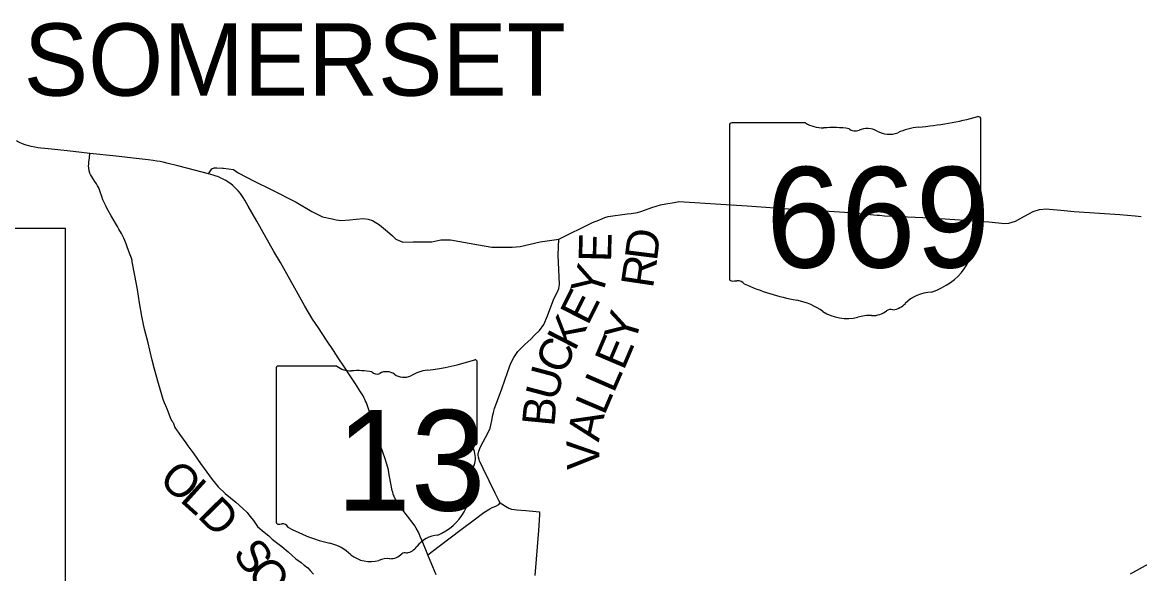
# Model space of a CAD drawing. Extents: x 1761803 to 2441803, y 509895 to 949895.
# Drawn here: x 2027446 to 2058370, y 738164 to 753419 of the extents above; entities that cross this region are included whole.
import ezdxf

# ---------------------------------------------------------------- set-up
doc = ezdxf.new("R2010")
doc.units = 0
for name, color, linetype in [('GM_X_County_Road', 7, 'Continuous'), ('GM_X_Minor_Lake', 7, 'Continuous'), ('GM_X_State_Location', 7, 'Continuous'), ('GM_X_Township_Road', 7, 'Continuous')]:
    doc.layers.add(name, color=color, linetype=linetype)

msp = doc.modelspace()

# ---------------------------------------------------------------- linework, layer by layer
at = {"layer": 'GM_X_County_Road'}
for points in [[(2039594, 739384), (2039954, 739654), (2040218, 739852), (2040380, 739960), (2040452, 739997), (2040553, 740031), (2040634, 740082), (2040672, 740126), (2040638, 740187), (2040533, 740390), (2040198, 741071), (2040099, 741288), (2040086, 741325), (2040068, 741389), (2040059, 741447), (2040061, 741475), (2040079, 741550), (2040126, 741670), (2040339, 742070), (2040393, 742194), (2040416, 742271), (2040441, 742402), (2040466, 742556), (2040484, 742627), (2040515, 742733), (2040721, 743277), (2040885, 743760), (2040969, 743987), (2041048, 744145), (2041156, 744311), (2041355, 744508), (2041516, 744655), (2041630, 744769), (2041761, 744895), (2041878, 745055), (2041977, 745301), (2042159, 745768), (2042268, 745980), (2042294, 746058), (2042314, 746164), (2042278, 746987), (2042296, 747418)], [(2031622, 742343), (2031670, 742205), (2031823, 741985), (2031970, 741780), (2032027, 741700), (2032194, 741483), (2032378, 741213), (2032551, 740968), (2032696, 740771), (2032862, 740563), (2033063, 740386), (2033350, 740138), (2033545, 739967), (2033672, 739853), (2033743, 739751), (2033843, 739634), (2033952, 739472), (2034097, 739347), (2034264, 739210), (2034361, 739118), (2034441, 739057), (2034519, 739001), (2034630, 738918), (2034799, 738772), (2034913, 738671), (2035016, 738579), (2035159, 738472), (2035245, 738397), (2035346, 738325), (2035414, 738255), (2035501, 738148)], [(2040672, 740126), (2040817, 740031), (2040912, 739977), (2040980, 739953), (2041131, 739928), (2041378, 739911), (2041665, 739882), (2041761, 739871)], [(2041761, 739871), (2041761, 739795), (2041730, 739361), (2041632, 738116)], [(2038673, 738681), (2038981, 738924), (2039594, 739384)]]:
    msp.add_lwpolyline(points, dxfattribs=at)
at = {"layer": 'GM_X_Minor_Lake'}
for points in [[(2029314, 749794), (2028855, 749843), (2028347, 749898), (2028069, 749928), (2027955, 749942), (2027875, 749951), (2027790, 749964), (2027693, 749981), (2027625, 749998), (2027555, 750018), (2027499, 750038), (2027431, 750065), (2027381, 750088), (2027315, 750121), (2027288, 750137)], [(2029510, 748931), (2029495, 748954), (2029452, 749018), (2029406, 749089), (2029359, 749164), (2029333, 749212), (2029318, 749247), (2029297, 749311), (2029282, 749390), (2029280, 749440), (2029282, 749497), (2029288, 749551), (2029300, 749667), (2029314, 749794)], [(2032601, 749227), (2031997, 749386), (2031753, 749451), (2031448, 749526), (2031345, 749548), (2031259, 749565), (2031167, 749582), (2031064, 749598), (2030931, 749617), (2030599, 749656), (2030042, 749715), (2029314, 749794)], [(2032601, 749227), (2032693, 749368), (2032752, 749390), (2032833, 749395), (2032985, 749385), (2033017, 749381)], [(2033017, 749381), (2033291, 749347), (2033423, 749259), (2033881, 749020), (2034330, 748790), (2035022, 748441), (2035462, 748190), (2035755, 748040), (2036017, 747985), (2036133, 747951), (2036256, 747933), (2036510, 747953), (2036686, 747975), (2036883, 747989), (2037015, 747971), (2037137, 747933), (2037327, 747820), (2037554, 747636), (2037690, 747514), (2037784, 747421), (2037974, 747341), (2038267, 747344), (2038783, 747350), (2039031, 747401), (2039169, 747404), (2039300, 747401), (2040070, 747263), (2040439, 747196), (2041002, 747196), (2041220, 747213), (2041780, 747347), (2042296, 747418), (2043224, 747880), (2043398, 747949), (2043568, 748019), (2043664, 748047), (2044184, 748119), (2044298, 748133), (2044467, 748155), (2044595, 748191), (2044865, 748293), (2045107, 748367), (2045255, 748395), (2045489, 748439), (2045577, 748455), (2045617, 748461), (2046058, 748437), (2046633, 748398), (2047506, 748339), (2048785, 748250), (2049640, 748208), (2050339, 748160), (2051101, 748087), (2051172, 748081), (2051310, 748069), (2052577, 748007), (2054191, 747896), (2054639, 747858), (2054751, 747864), (2054931, 747914), (2055186, 748058), (2055424, 748190), (2055598, 748238), (2055792, 748258), (2055871, 748252), (2056188, 748226), (2056559, 748190), (2057822, 748101), (2058247, 748065), (2058411, 748043)], [(2033700, 748332), (2033654, 748414), (2033600, 748501), (2033555, 748574), (2033518, 748631), (2033479, 748683), (2033422, 748753), (2033372, 748808), (2033330, 748848), (2033267, 748905), (2033215, 748947), (2033138, 749000), (2033075, 749041), (2033004, 749080), (2032957, 749103), (2032891, 749132), (2032850, 749150), (2032806, 749165), (2032728, 749190), (2032601, 749227)], [(2031622, 742343), (2031604, 742369), (2031588, 742393), (2031566, 742430), (2031546, 742475), (2031507, 742576), (2031460, 742694), (2031414, 742804), (2031381, 742888), (2031345, 742987), (2031309, 743109), (2031217, 743425), (2031107, 743820), (2031041, 744071), (2030974, 744350), (2030925, 744555), (2030826, 744929), (2030788, 745105), (2030755, 745287), (2030692, 745662), (2030631, 746028), (2030560, 746412), (2030489, 746795), (2030483, 746826), (2030465, 746890), (2030432, 746985), (2030359, 747184), (2030320, 747287), (2030281, 747385), (2030253, 747449), (2030190, 747574), (2030119, 747698), (2030078, 747771), (2029902, 748068), (2029820, 748212), (2029781, 748281), (2029752, 748339), (2029715, 748420), (2029677, 748511), (2029648, 748598), (2029602, 748733), (2029583, 748786), (2029560, 748839), (2029530, 748897), (2029510, 748931)], [(2038902, 738130), (2038807, 738356), (2038737, 738526), (2038673, 738681), (2038531, 739022), (2038503, 739090), (2038460, 739190), (2038428, 739266), (2038407, 739310), (2038346, 739424), (2038307, 739487), (2038262, 739551), (2038104, 739758), (2037953, 739955), (2037876, 740058), (2037843, 740106), (2037791, 740189), (2037767, 740235), (2037738, 740302), (2037713, 740364), (2037697, 740420), (2037684, 740469), (2037639, 740703), (2037593, 740958), (2037577, 741034), (2037558, 741100), (2037483, 741343), (2037362, 741709), (2037252, 742035), (2037158, 742321), (2037060, 742615), (2036967, 742888), (2036946, 742941), (2036929, 742981), (2036910, 743021), (2036878, 743082), (2036805, 743200), (2036663, 743415), (2036573, 743551), (2036534, 743612), (2036358, 743881), (2036188, 744139), (2036055, 744338), (2035863, 744629), (2035639, 744963), (2035477, 745209), (2035267, 745563), (2035035, 745977), (2034587, 746772), (2034410, 747081), (2033932, 747921), (2033700, 748332)], [(2058113, 738160), (2058182, 738196), (2058634, 738445)]]:
    msp.add_lwpolyline(points, dxfattribs=at)
at = {"layer": 'GM_X_State_Location'}
msp.add_lwpolyline([(1999264, 732882), (2028640, 732882), (2028640, 747716), (1999264, 747716)], close=True, dxfattribs=at)
at = {"layer": 'GM_X_Township_Road'}
for p, q in [((2047014, 750563), (2047014, 746336)), ((2049121, 750635), (2047082, 750635)), ((2053974, 748529), (2053974, 750740)), ((2053974, 748530), (2053974, 748529)), ((2034467, 743837), (2034467, 739610)), ((2036153, 743909), (2034522, 743909)), ((2040036, 741803), (2040036, 744014)), ((2040036, 741804), (2040036, 741803))]:
    msp.add_line(p, q, dxfattribs=at)
for centre, radius, start, end in [((2038052, 749671), 5905, 275.8445, 288.9065), ((2039974, 744023), 62, 351.8621, 97.738), ((2034531, 743846), 64.5, 98.1301, 188.1301), ((2036541, 744400), 626, 231.6195, 271.1119), ((2036749, 741536), 2246, 80.4867, 94.9883), ((2037259, 743867), 181, 219.7921, 297.1024), ((2037524, 743379), 375, 54.4667, 119.1411), ((2038806, 742618), 1188, 97.3462, 120.7689), ((2038008, 744049), 452, 233.8562, 294.8282), ((2040022, 741641), 95.9, 107.944, 210.337), ((2039411, 741361), 576, 340.033, 23.6496), ((2039970, 741795), 66.3, 289.6038, 7.7341), ((2040258, 740878), 419, 136.8065, 186.9296), ((2038383, 740597), 1477, 292.3089, 8.9858), ((2034532, 739601), 65.1, 171.9584, 258.3066), ((2034542, 740033), 497, 267.339, 280.6039), ((2034643, 739366), 179, 29.7484, 93.2717), ((2036904, 743164), 4265, 240.4129, 257.1985), ((2039006, 738423), 809, 94.4031, 142.5768), ((2035633, 737711), 1334, 47.1842, 75.836), ((2037981, 739200), 477, 282.8732, 323.2771), ((2037076, 739345), 847, 230.7004, 286.2918), ((2037565, 737884), 696, 85.6951, 111.2099), ((2037627, 739029), 451, 268.777, 315.5493), ((2038035, 738619), 127, 65.7517, 132.6484)]:
    msp.add_arc(centre, radius, start, end, dxfattribs=at)
for centre, major_axis, start_param, end_param in [((2047093, 750572), (80.6, 0), 1.712693, 3.28349), ((2049606, 751126), (782, 0), 4.042523, 4.731795), ((2051495, 756397), (7382, 0), 4.814394, 5.042369), ((2053897, 750749), (77.5, 0), 6.141152, 7.989035), ((2049865, 748262), (2808, 0), 1.404758, 1.657858), ((2050503, 750593), (226, 0), 3.836095, 5.185415), ((2050834, 750105), (469, 0), 0.950623, 2.079405), ((2051440, 750775), (564, 0), 4.081561, 5.145723), ((2052436, 749344), (1485, 0), 1.699011, 2.107814), ((2053957, 748367), (120, 0), 1.883978, 3.671073), ((2053892, 748521), (82.9, 0), 5.05454, 6.418171), ((2053194, 748087), (720, 0), 5.934695, 6.695948), ((2054252, 747604), (524, 0), 2.387724, 3.262537), ((2051908, 747323), (1846, 0), 5.101752, 6.440018), ((2047094, 746327), (81.4, 0), 3.00124, 4.508301), ((2047106, 746759), (621, 0), 4.665946, 4.897461), ((2047233, 746092), (224, 0), 0.519207, 1.627899), ((2050060, 749890), (5331, 0), 4.195997, 4.488961), ((2052687, 745149), (1011, 0), 1.647645, 2.488434), ((2048471, 744437), (1668, 0), 0.823519, 1.323587), ((2051406, 745926), (597, 0), 4.937069, 5.64225), ((2050274, 746071), (1058, 0), 4.026481, 4.996735), ((2050886, 744610), (870, 0), 1.495662, 1.94098), ((2050963, 745755), (564, 0), 4.691044, 5.507374), ((2051473, 745345), (159, 0), 1.147584, 2.315152)]:
    msp.add_ellipse(centre, major_axis=major_axis, ratio=0.8, start_param=start_param, end_param=end_param, dxfattribs=at)

# ---------------------------------------------------------------- texts
at = {"layer": 'GM_X_County_Road'}
for s, height, rotation, p in [('SOMERSET', 2000, 0, (2027482, 751390)), ('E', 900, 88.5312, (2043739, 746781)), ('D', 900, 82.8998, (2045009, 746795)), ('R', 900, 81.5427, (2044897, 746041)), ('Y', 900, 72.6558, (2043459, 745757)), ('E', 900, 63.2352, (2043095, 745007)), ('K', 900, 63.0152, (2042734, 744297)), ('Y', 900, 73.4659, (2044387, 744489)), ('C', 900, 64.5545, (2042419, 743636)), ('E', 900, 67.0283, (2044087, 743765)), ('U', 900, 75.137, (2042231, 742911)), ('L', 900, 66.4142, (2043813, 743138)), ('L', 900, 66.9688, (2043551, 742521)), ('B', 900, 84.4554, (2042167, 742214)), ('A', 900, 77.9392, (2043399, 741790)), ('V', 900, 91.2777, (2043422, 741053)), ('O', 900, 318.1054, (2031188, 740714)), ('L', 900, 317.9347, (2031777, 740185)), ('D', 900, 314.812, (2032268, 739743)), ('S', 900, 305.0225, (2033247, 738725)), ('O', 900, 308.7423, (2033633, 738176))]:
    msp.add_text(s, height=height, rotation=rotation, dxfattribs=at).set_placement(p)
at = {"layer": 'GM_X_Township_Road'}
for s, p in [('669', (2048026, 746634)), ('13', (2036125, 739908))]:
    msp.add_text(s, height=2784.4, dxfattribs=at).set_placement(p)

doc.saveas('drawing.dxf')
